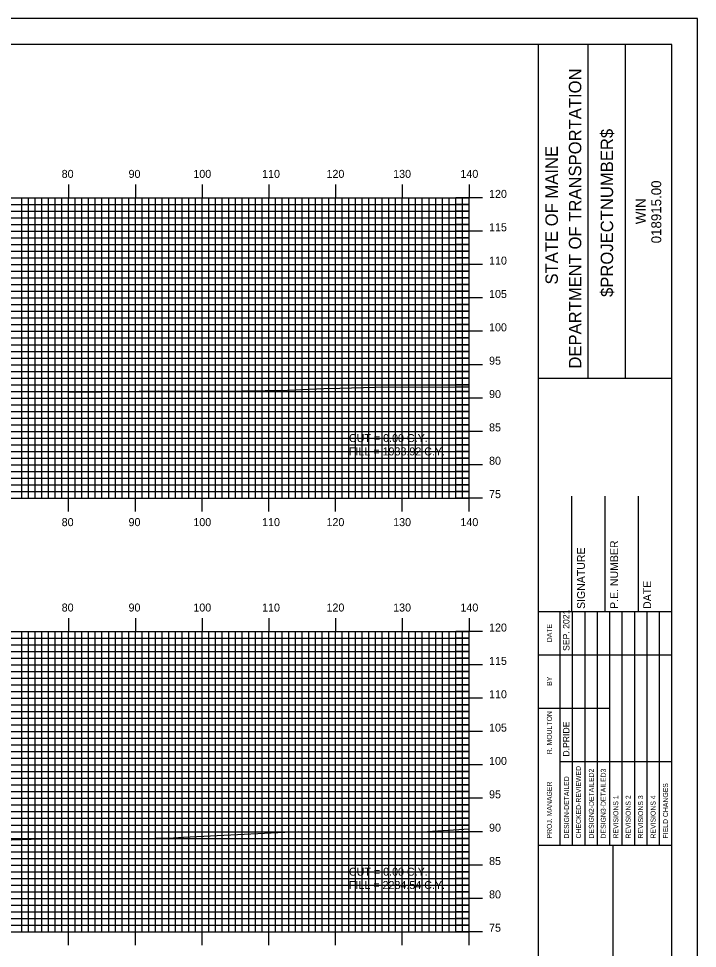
# Model space of a CAD drawing. Extents: x 485 to 829, y -1658 to -1438.
# Drawn here: x 723.6 to 825.3, y -1577.1 to -1437.7 of the extents above; entities that cross this region are included whole.
import ezdxf

# ---------------------------------------------------------------- set-up
doc = ezdxf.new("R2010")
doc.units = 0
for name, color, linetype in [('BORDER', 7, 'Continuous'), ('D_Text_Standard', 7, 'Continuous'), ('H_V ANNOTATION', 7, 'Continuous'), ('MAJOR', 7, 'Continuous'), ('MINOR', 7, 'Continuous'), ('PLOT BOUNDARY', 7, 'Continuous'), ('S_Roadway_Centerline', 7, 'Continuous')]:
    doc.layers.add(name, color=color, linetype=linetype)

msp = doc.modelspace()

# ---------------------------------------------------------------- linework, layer by layer
at = {"layer": 'BORDER'}
for p, q in [((801.53, -1651.6), (801.53, -1441.6)), ((808.99, -1491.61), (808.99, -1441.61)), ((814.58, -1491.61), (814.58, -1441.61)), ((801.54, -1491.62), (821.53, -1491.62)), ((806.53, -1526.6), (806.53, -1509.3)), ((811.53, -1526.6), (811.53, -1509.3)), ((816.53, -1526.6), (816.53, -1509.3)), ((801.53, -1526.6), (821.53, -1526.6)), ((801.53, -1561.6), (821.53, -1561.6)), ((812.72, -1631.6), (812.72, -1561.6))]:
    msp.add_line(p, q, dxfattribs=at)
msp.add_lwpolyline([(501.53, -1651.6), (821.53, -1651.6), (821.53, -1441.6), (501.53, -1441.6)], close=True, dxfattribs=at)
for points in [[(804.76, -1533.1), (804.76, -1526.6)], [(806.63, -1561.59), (806.63, -1526.6)], [(808.49, -1526.6), (808.49, -1561.59)], [(810.36, -1561.59), (810.36, -1526.6)], [(812.22, -1561.59), (812.22, -1526.6)], [(814.08, -1561.59), (814.08, -1526.6)], [(815.95, -1561.59), (815.95, -1526.6)], [(817.81, -1561.59), (817.81, -1526.6)], [(819.67, -1561.59), (819.67, -1526.6)], [(804.77, -1561.59), (804.77, -1528.01)], [(801.53, -1533.1), (821.53, -1533.1)], [(801.53, -1541.1), (804.77, -1541.1)], [(804.76, -1541.1), (812.22, -1541.1)], [(804.76, -1549.1), (821.53, -1549.1)]]:
    msp.add_lwpolyline(points, dxfattribs=at)
at = {"layer": 'MAJOR'}
for p, q in [((731.13, -1462.6), (731.13, -1464.6)), ((741.13, -1462.6), (741.13, -1464.6)), ((751.13, -1462.6), (751.13, -1464.6)), ((761.13, -1462.6), (761.13, -1464.6)), ((771.13, -1462.6), (771.13, -1464.6)), ((781.13, -1462.6), (781.13, -1464.6)), ((791.13, -1462.6), (791.13, -1464.6)), ((511.13, -1464.6), (791.13, -1464.6)), ((511.13, -1464.6), (791.13, -1464.6)), ((731.13, -1509.6), (731.13, -1464.6)), ((741.13, -1509.6), (741.13, -1464.6)), ((751.13, -1509.6), (751.13, -1464.6)), ((761.13, -1509.6), (761.13, -1464.6)), ((771.13, -1509.6), (771.13, -1464.6)), ((781.13, -1509.6), (781.13, -1464.6)), ((793.14, -1464.6), (789.13, -1464.6)), ((791.13, -1509.6), (791.13, -1464.6)), ((791.13, -1509.6), (791.13, -1464.6)), ((511.13, -1469.6), (791.13, -1469.6)), ((793.14, -1469.6), (789.13, -1469.6)), ((511.13, -1474.6), (791.13, -1474.6)), ((793.14, -1474.6), (789.13, -1474.6)), ((511.13, -1479.6), (791.13, -1479.6)), ((793.14, -1479.6), (789.13, -1479.6)), ((511.13, -1484.6), (791.13, -1484.6)), ((793.14, -1484.6), (789.13, -1484.6)), ((511.13, -1489.6), (791.13, -1489.6)), ((793.14, -1489.6), (789.13, -1489.6)), ((511.13, -1494.6), (791.13, -1494.6)), ((793.14, -1494.6), (789.13, -1494.6)), ((511.13, -1499.6), (791.13, -1499.6)), ((793.14, -1499.6), (789.13, -1499.6)), ((511.13, -1504.6), (791.13, -1504.6)), ((793.14, -1504.6), (789.13, -1504.6)), ((511.13, -1509.6), (791.13, -1509.6)), ((511.13, -1509.6), (791.13, -1509.6)), ((731.13, -1511.61), (731.13, -1509.6)), ((741.13, -1511.61), (741.13, -1509.6)), ((751.13, -1511.61), (751.13, -1509.6)), ((761.13, -1511.61), (761.13, -1509.6)), ((771.13, -1511.61), (771.13, -1509.6)), ((781.13, -1511.61), (781.13, -1509.6)), ((793.14, -1509.6), (789.13, -1509.6)), ((791.13, -1511.61), (791.13, -1509.6)), ((731.13, -1527.6), (731.13, -1529.6)), ((741.13, -1527.6), (741.13, -1529.6)), ((751.13, -1527.6), (751.13, -1529.6)), ((761.13, -1527.6), (761.13, -1529.6)), ((771.13, -1527.6), (771.13, -1529.6)), ((781.13, -1527.6), (781.13, -1529.6)), ((791.13, -1527.6), (791.13, -1529.6)), ((511.13, -1529.6), (791.13, -1529.6)), ((511.13, -1529.6), (791.13, -1529.6)), ((731.13, -1574.6), (731.13, -1529.6)), ((741.13, -1574.6), (741.13, -1529.6)), ((751.13, -1574.6), (751.13, -1529.6)), ((761.13, -1574.6), (761.13, -1529.6)), ((771.13, -1574.6), (771.13, -1529.6)), ((781.13, -1574.6), (781.13, -1529.6)), ((793.14, -1529.6), (789.13, -1529.6)), ((791.13, -1574.6), (791.13, -1529.6)), ((791.13, -1574.6), (791.13, -1529.6)), ((511.13, -1534.6), (791.13, -1534.6)), ((793.14, -1534.6), (789.13, -1534.6)), ((511.13, -1539.6), (791.13, -1539.6)), ((793.14, -1539.6), (789.13, -1539.6)), ((511.13, -1544.6), (791.13, -1544.6)), ((793.14, -1544.6), (789.13, -1544.6)), ((511.13, -1549.6), (791.13, -1549.6)), ((793.14, -1549.6), (789.13, -1549.6)), ((511.13, -1554.6), (791.13, -1554.6)), ((793.14, -1554.6), (789.13, -1554.6)), ((511.13, -1559.6), (791.13, -1559.6)), ((793.14, -1559.6), (789.13, -1559.6)), ((511.13, -1564.6), (791.13, -1564.6)), ((793.14, -1564.6), (789.13, -1564.6)), ((511.13, -1569.6), (791.13, -1569.6)), ((793.14, -1569.6), (789.13, -1569.6)), ((511.13, -1574.6), (791.13, -1574.6)), ((511.13, -1574.6), (791.13, -1574.6)), ((731.13, -1576.61), (731.13, -1574.6)), ((741.13, -1576.61), (741.13, -1574.6)), ((751.13, -1576.61), (751.13, -1574.6)), ((761.13, -1576.61), (761.13, -1574.6)), ((771.13, -1576.61), (771.13, -1574.6)), ((781.13, -1576.61), (781.13, -1574.6)), ((793.14, -1574.6), (789.13, -1574.6)), ((791.13, -1576.61), (791.13, -1574.6))]:
    msp.add_line(p, q, dxfattribs=at)
at = {"layer": 'MINOR'}
for p, q in [((724.13, -1509.6), (724.13, -1464.6)), ((725.13, -1509.6), (725.13, -1464.6)), ((726.13, -1509.6), (726.13, -1464.6)), ((727.13, -1509.6), (727.13, -1464.6)), ((728.13, -1509.6), (728.13, -1464.6)), ((729.13, -1509.6), (729.13, -1464.6)), ((730.13, -1509.6), (730.13, -1464.6)), ((732.13, -1509.6), (732.13, -1464.6)), ((733.13, -1509.6), (733.13, -1464.6)), ((734.13, -1509.6), (734.13, -1464.6)), ((735.13, -1509.6), (735.13, -1464.6)), ((736.13, -1509.6), (736.13, -1464.6)), ((737.13, -1509.6), (737.13, -1464.6)), ((738.13, -1509.6), (738.13, -1464.6)), ((739.13, -1509.6), (739.13, -1464.6)), ((740.13, -1509.6), (740.13, -1464.6)), ((742.13, -1509.6), (742.13, -1464.6)), ((743.13, -1509.6), (743.13, -1464.6)), ((744.13, -1509.6), (744.13, -1464.6)), ((745.13, -1509.6), (745.13, -1464.6)), ((746.13, -1509.6), (746.13, -1464.6)), ((747.13, -1509.6), (747.13, -1464.6)), ((748.13, -1509.6), (748.13, -1464.6)), ((749.13, -1509.6), (749.13, -1464.6)), ((750.13, -1509.6), (750.13, -1464.6)), ((752.13, -1509.6), (752.13, -1464.6)), ((753.13, -1509.6), (753.13, -1464.6)), ((754.13, -1509.6), (754.13, -1464.6)), ((755.13, -1509.6), (755.13, -1464.6)), ((756.13, -1509.6), (756.13, -1464.6)), ((757.13, -1509.6), (757.13, -1464.6)), ((758.13, -1509.6), (758.13, -1464.6)), ((759.13, -1509.6), (759.13, -1464.6)), ((760.13, -1509.6), (760.13, -1464.6)), ((762.13, -1509.6), (762.13, -1464.6)), ((763.13, -1509.6), (763.13, -1464.6)), ((764.13, -1509.6), (764.13, -1464.6)), ((765.13, -1509.6), (765.13, -1464.6)), ((766.13, -1509.6), (766.13, -1464.6)), ((767.13, -1509.6), (767.13, -1464.6)), ((768.13, -1509.6), (768.13, -1464.6)), ((769.13, -1509.6), (769.13, -1464.6)), ((770.13, -1509.6), (770.13, -1464.6)), ((772.13, -1509.6), (772.13, -1464.6)), ((773.13, -1509.6), (773.13, -1464.6)), ((774.13, -1509.6), (774.13, -1464.6)), ((775.13, -1509.6), (775.13, -1464.6)), ((776.13, -1509.6), (776.13, -1464.6)), ((777.13, -1509.6), (777.13, -1464.6)), ((778.13, -1509.6), (778.13, -1464.6)), ((779.13, -1509.6), (779.13, -1464.6)), ((780.13, -1509.6), (780.13, -1464.6)), ((782.13, -1509.6), (782.13, -1464.6)), ((783.13, -1509.6), (783.13, -1464.6)), ((784.13, -1509.6), (784.13, -1464.6)), ((785.13, -1509.6), (785.13, -1464.6)), ((786.13, -1509.6), (786.13, -1464.6)), ((787.13, -1509.6), (787.13, -1464.6)), ((788.13, -1509.6), (788.13, -1464.6)), ((789.13, -1509.6), (789.13, -1464.6)), ((790.13, -1509.6), (790.13, -1464.6)), ((511.13, -1465.6), (791.13, -1465.6)), ((791.13, -1465.6), (789.13, -1465.6)), ((511.13, -1466.6), (791.13, -1466.6)), ((511.13, -1467.6), (791.13, -1467.6)), ((791.13, -1466.6), (789.13, -1466.6)), ((791.13, -1467.6), (789.13, -1467.6)), ((511.13, -1468.6), (791.13, -1468.6)), ((791.13, -1468.6), (789.13, -1468.6)), ((511.13, -1470.6), (791.13, -1470.6)), ((511.13, -1471.6), (791.13, -1471.6)), ((791.13, -1470.6), (789.13, -1470.6)), ((791.13, -1471.6), (789.13, -1471.6)), ((511.13, -1472.6), (791.13, -1472.6)), ((791.13, -1472.6), (789.13, -1472.6)), ((511.13, -1473.6), (791.13, -1473.6)), ((791.13, -1473.6), (789.13, -1473.6)), ((511.13, -1475.6), (791.13, -1475.6)), ((791.13, -1475.6), (789.13, -1475.6)), ((511.13, -1476.6), (791.13, -1476.6)), ((791.13, -1476.6), (789.13, -1476.6)), ((511.13, -1477.6), (791.13, -1477.6)), ((511.13, -1478.6), (791.13, -1478.6)), ((791.13, -1477.6), (789.13, -1477.6)), ((791.13, -1478.6), (789.13, -1478.6)), ((511.13, -1480.6), (791.13, -1480.6)), ((791.13, -1480.6), (789.13, -1480.6)), ((511.13, -1481.6), (791.13, -1481.6)), ((511.13, -1482.6), (791.13, -1482.6)), ((791.13, -1481.6), (789.13, -1481.6)), ((791.13, -1482.6), (789.13, -1482.6)), ((511.13, -1483.6), (791.13, -1483.6)), ((791.13, -1483.6), (789.13, -1483.6)), ((511.13, -1485.6), (791.13, -1485.6)), ((791.13, -1485.6), (789.13, -1485.6)), ((511.13, -1486.6), (791.13, -1486.6)), ((791.13, -1486.6), (789.13, -1486.6)), ((511.13, -1487.6), (791.13, -1487.6)), ((791.13, -1487.6), (789.13, -1487.6)), ((511.13, -1488.6), (791.13, -1488.6)), ((791.13, -1488.6), (789.13, -1488.6)), ((511.13, -1490.6), (791.13, -1490.6)), ((791.13, -1490.6), (789.13, -1490.6)), ((511.13, -1491.6), (791.13, -1491.6)), ((511.13, -1492.6), (791.13, -1492.6)), ((791.13, -1491.6), (789.13, -1491.6)), ((791.13, -1492.6), (789.13, -1492.6)), ((511.13, -1493.6), (791.13, -1493.6)), ((791.13, -1493.6), (789.13, -1493.6)), ((511.13, -1495.6), (791.13, -1495.6)), ((511.13, -1496.6), (791.13, -1496.6)), ((791.13, -1495.6), (789.13, -1495.6)), ((791.13, -1496.6), (789.13, -1496.6)), ((511.13, -1497.6), (791.13, -1497.6)), ((791.13, -1497.6), (789.13, -1497.6)), ((511.13, -1498.6), (791.13, -1498.6)), ((791.13, -1498.6), (789.13, -1498.6)), ((511.13, -1500.6), (791.13, -1500.6)), ((791.13, -1500.6), (789.13, -1500.6)), ((511.13, -1501.6), (791.13, -1501.6)), ((791.13, -1501.6), (789.13, -1501.6)), ((511.13, -1502.6), (791.13, -1502.6)), ((511.13, -1503.6), (791.13, -1503.6)), ((791.13, -1502.6), (789.13, -1502.6)), ((791.13, -1503.6), (789.13, -1503.6)), ((511.13, -1505.6), (791.13, -1505.6)), ((511.13, -1506.6), (791.13, -1506.6)), ((791.13, -1505.6), (789.13, -1505.6)), ((791.13, -1506.6), (789.13, -1506.6)), ((511.13, -1507.6), (791.13, -1507.6)), ((791.13, -1507.6), (789.13, -1507.6)), ((511.13, -1508.6), (791.13, -1508.6)), ((791.13, -1508.6), (789.13, -1508.6)), ((724.13, -1574.6), (724.13, -1529.6)), ((725.13, -1574.6), (725.13, -1529.6)), ((726.13, -1574.6), (726.13, -1529.6)), ((727.13, -1574.6), (727.13, -1529.6)), ((728.13, -1574.6), (728.13, -1529.6)), ((729.13, -1574.6), (729.13, -1529.6)), ((730.13, -1574.6), (730.13, -1529.6)), ((732.13, -1574.6), (732.13, -1529.6)), ((733.13, -1574.6), (733.13, -1529.6)), ((734.13, -1574.6), (734.13, -1529.6)), ((735.13, -1574.6), (735.13, -1529.6)), ((736.13, -1574.6), (736.13, -1529.6)), ((737.13, -1574.6), (737.13, -1529.6)), ((738.13, -1574.6), (738.13, -1529.6)), ((739.13, -1574.6), (739.13, -1529.6)), ((740.13, -1574.6), (740.13, -1529.6)), ((742.13, -1574.6), (742.13, -1529.6)), ((743.13, -1574.6), (743.13, -1529.6)), ((744.13, -1574.6), (744.13, -1529.6)), ((745.13, -1574.6), (745.13, -1529.6)), ((746.13, -1574.6), (746.13, -1529.6)), ((747.13, -1574.6), (747.13, -1529.6)), ((748.13, -1574.6), (748.13, -1529.6)), ((749.13, -1574.6), (749.13, -1529.6)), ((750.13, -1574.6), (750.13, -1529.6)), ((752.13, -1574.6), (752.13, -1529.6)), ((753.13, -1574.6), (753.13, -1529.6)), ((754.13, -1574.6), (754.13, -1529.6)), ((755.13, -1574.6), (755.13, -1529.6)), ((756.13, -1574.6), (756.13, -1529.6)), ((757.13, -1574.6), (757.13, -1529.6)), ((758.13, -1574.6), (758.13, -1529.6)), ((759.13, -1574.6), (759.13, -1529.6)), ((760.13, -1574.6), (760.13, -1529.6)), ((762.13, -1574.6), (762.13, -1529.6)), ((763.13, -1574.6), (763.13, -1529.6)), ((764.13, -1574.6), (764.13, -1529.6)), ((765.13, -1574.6), (765.13, -1529.6)), ((766.13, -1574.6), (766.13, -1529.6)), ((767.13, -1574.6), (767.13, -1529.6)), ((768.13, -1574.6), (768.13, -1529.6)), ((769.13, -1574.6), (769.13, -1529.6)), ((770.13, -1574.6), (770.13, -1529.6)), ((772.13, -1574.6), (772.13, -1529.6)), ((773.13, -1574.6), (773.13, -1529.6)), ((774.13, -1574.6), (774.13, -1529.6)), ((775.13, -1574.6), (775.13, -1529.6)), ((776.13, -1574.6), (776.13, -1529.6)), ((777.13, -1574.6), (777.13, -1529.6)), ((778.13, -1574.6), (778.13, -1529.6)), ((779.13, -1574.6), (779.13, -1529.6)), ((780.13, -1574.6), (780.13, -1529.6)), ((782.13, -1574.6), (782.13, -1529.6)), ((783.13, -1574.6), (783.13, -1529.6)), ((784.13, -1574.6), (784.13, -1529.6)), ((785.13, -1574.6), (785.13, -1529.6)), ((786.13, -1574.6), (786.13, -1529.6)), ((787.13, -1574.6), (787.13, -1529.6)), ((788.13, -1574.6), (788.13, -1529.6)), ((789.13, -1574.6), (789.13, -1529.6)), ((790.13, -1574.6), (790.13, -1529.6)), ((511.13, -1530.6), (791.13, -1530.6)), ((511.13, -1531.6), (791.13, -1531.6)), ((791.13, -1530.6), (789.13, -1530.6)), ((791.13, -1531.6), (789.13, -1531.6)), ((511.13, -1532.6), (791.13, -1532.6)), ((791.13, -1532.6), (789.13, -1532.6)), ((511.13, -1533.6), (791.13, -1533.6)), ((791.13, -1533.6), (789.13, -1533.6)), ((511.13, -1535.6), (791.13, -1535.6)), ((791.13, -1535.6), (789.13, -1535.6)), ((511.13, -1536.6), (791.13, -1536.6)), ((791.13, -1536.6), (789.13, -1536.6)), ((511.13, -1537.6), (791.13, -1537.6)), ((511.13, -1538.6), (791.13, -1538.6)), ((791.13, -1537.6), (789.13, -1537.6)), ((791.13, -1538.6), (789.13, -1538.6)), ((511.13, -1540.6), (791.13, -1540.6)), ((791.13, -1540.6), (789.13, -1540.6)), ((511.13, -1541.6), (791.13, -1541.6)), ((511.13, -1542.6), (791.13, -1542.6)), ((791.13, -1541.6), (789.13, -1541.6)), ((791.13, -1542.6), (789.13, -1542.6)), ((511.13, -1543.6), (791.13, -1543.6)), ((791.13, -1543.6), (789.13, -1543.6)), ((511.13, -1545.6), (791.13, -1545.6)), ((791.13, -1545.6), (789.13, -1545.6)), ((511.13, -1546.6), (791.13, -1546.6)), ((791.13, -1546.6), (789.13, -1546.6)), ((511.13, -1547.6), (791.13, -1547.6)), ((791.13, -1547.6), (789.13, -1547.6)), ((511.13, -1548.6), (791.13, -1548.6)), ((791.13, -1548.6), (789.13, -1548.6)), ((511.13, -1550.6), (791.13, -1550.6)), ((791.13, -1550.6), (789.13, -1550.6)), ((511.13, -1551.6), (791.13, -1551.6)), ((511.13, -1552.6), (791.13, -1552.6)), ((791.13, -1551.6), (789.13, -1551.6)), ((791.13, -1552.6), (789.13, -1552.6)), ((511.13, -1553.6), (791.13, -1553.6)), ((791.13, -1553.6), (789.13, -1553.6)), ((511.13, -1555.6), (791.13, -1555.6)), ((511.13, -1556.6), (791.13, -1556.6)), ((791.13, -1555.6), (789.13, -1555.6)), ((791.13, -1556.6), (789.13, -1556.6)), ((511.13, -1557.6), (791.13, -1557.6)), ((791.13, -1557.6), (789.13, -1557.6)), ((511.13, -1558.6), (791.13, -1558.6)), ((791.13, -1558.6), (789.13, -1558.6)), ((511.13, -1560.6), (791.13, -1560.6)), ((791.13, -1560.6), (789.13, -1560.6)), ((511.13, -1561.6), (791.13, -1561.6)), ((791.13, -1561.6), (789.13, -1561.6)), ((511.13, -1562.6), (791.13, -1562.6)), ((511.13, -1563.6), (791.13, -1563.6)), ((791.13, -1562.6), (789.13, -1562.6)), ((791.13, -1563.6), (789.13, -1563.6)), ((511.13, -1565.6), (791.13, -1565.6)), ((791.13, -1565.6), (789.13, -1565.6)), ((511.13, -1566.6), (791.13, -1566.6)), ((511.13, -1567.6), (791.13, -1567.6)), ((791.13, -1566.6), (789.13, -1566.6)), ((791.13, -1567.6), (789.13, -1567.6)), ((511.13, -1568.6), (791.13, -1568.6)), ((791.13, -1568.6), (789.13, -1568.6)), ((511.13, -1570.6), (791.13, -1570.6)), ((791.13, -1570.6), (789.13, -1570.6)), ((511.13, -1571.6), (791.13, -1571.6)), ((791.13, -1571.6), (789.13, -1571.6)), ((511.13, -1572.6), (791.13, -1572.6)), ((791.13, -1572.6), (789.13, -1572.6)), ((511.13, -1573.6), (791.13, -1573.6)), ((791.13, -1573.6), (789.13, -1573.6))]:
    msp.add_line(p, q, dxfattribs=at)
at = {"layer": 'PLOT BOUNDARY'}
msp.add_lwpolyline([(485.35, -1657.72), (825.35, -1657.72), (825.35, -1437.72), (485.35, -1437.72)], close=True, dxfattribs=at)
at = {"layer": 'S_Roadway_Centerline'}
for points in [[(616.3, -1496.46), (624.98, -1495.99), (629.65, -1495.69), (631.37, -1495.68), (634.77, -1495.54), (648.43, -1495.02), (654.32, -1494.89), (666.18, -1494.54), (672.13, -1494.58), (682.88, -1494.63), (692.81, -1494.19), (701.22, -1494.02), (717.87, -1493.58), (719.17, -1493.55), (731.05, -1493.68), (736.02, -1493.66), (744.54, -1493.54), (753.83, -1493.55), (763.95, -1493.4), (769.39, -1493.17), (771.76, -1493.11), (777.05, -1492.99), (789.2, -1492.93), (791.13, -1492.91)], [(615.91, -1562.69), (624.29, -1562.57), (635.21, -1562.36), (640.02, -1562.14), (653.7, -1561.78), (660.67, -1561.89), (672.76, -1561.52), (674.18, -1561.52), (691.05, -1561.68), (707.38, -1561.38), (708.44, -1561.35), (709.09, -1561.34), (721.14, -1560.85), (728.42, -1560.62), (733.48, -1560.61), (744.15, -1560.57), (745.48, -1560.57), (746.09, -1560.57), (748.34, -1560.42), (765.53, -1559.55), (778.36, -1559.61), (784.09, -1559.62), (791.13, -1559.17)]]:
    msp.add_lwpolyline(points, dxfattribs=at)

# ---------------------------------------------------------------- texts
at = {"layer": 'BORDER'}
for s, height, p in [('DEPARTMENT OF TRANSPORTATION', 1.8635, (807.95, -1490.19)), ('$PROJECTNUMBER$', 1.8635, (812.72, -1479.45)), ('STATE OF MAINE', 1.8635, (804.44, -1477.58)), ('018915.00', 1.491, (819.93, -1471.41)), ('WIN', 1.491, (817.61, -1468.54)), ('P.E. NUMBER', 1.1811, (813.46, -1526.21)), ('SIGNATURE', 1.181, (808.5, -1526.21)), ('DATE', 1.181, (818.42, -1526.21)), ('SEP. 2021', 0.969, (806.18, -1532.51)), ('DATE', 0.743, (803.54, -1531.19)), ('BY', 0.743, (803.54, -1537.73)), ('R. MOULTON', 0.745, (803.54, -1547.99)), ('D.PRIDE', 0.969, (806.18, -1548.35)), ('CHECKED-REVIEWED', 0.7455, (807.9, -1560.62)), ('DESIGN2-DETAILED2', 0.7455, (809.83, -1560.62)), ('DESIGN3-DETAILED3', 0.7455, (811.62, -1560.62)), ('PROJ. MANAGER', 0.7455, (803.54, -1560.62)), ('DESIGN-DETAILED', 0.7455, (806.11, -1560.62)), ('FIELD CHANGES', 0.7455, (820.94, -1560.62)), ('REVISIONS 1', 0.7455, (813.49, -1560.62)), ('REVISIONS 2', 0.7455, (815.35, -1560.62)), ('REVISIONS 3', 0.7455, (817.21, -1560.62)), ('REVISIONS 4', 0.7455, (819.08, -1560.62))]:
    msp.add_text(s, height=height, rotation=90, dxfattribs=at).set_placement(p)
at = {"layer": 'D_Text_Standard'}
for s, p in [('CUT = 0.00 C.Y.', (773.13, -1501.2)), ('FILL = 1933.92 C.Y.', (773.13, -1503.2)), ('CUT = 0.00 C.Y.', (773.13, -1566.2)), ('FILL = 2284.54 C.Y.', (773.13, -1568.2))]:
    msp.add_text(s, height=1.2, dxfattribs=at).set_placement(p)
at = {"layer": 'H_V ANNOTATION'}
for s, p in [('80', (730.09, -1461.6)), ('90', (740.11, -1461.6)), ('100', (749.82, -1461.6)), ('110', (760.12, -1461.6)), ('120', (769.77, -1461.6)), ('130', (779.76, -1461.6)), ('140', (789.84, -1461.6)), ('120', (794.13, -1464.6)), ('115', (794.13, -1469.6)), ('110', (794.13, -1474.6)), ('105', (794.13, -1479.6)), ('100', (794.13, -1484.6)), ('95', (794.13, -1489.6)), ('90', (794.13, -1494.6)), ('85', (794.13, -1499.6)), ('80', (794.13, -1504.6)), ('75', (794.13, -1509.6)), ('80', (730.09, -1513.8)), ('90', (740.11, -1513.8)), ('100', (749.82, -1513.8)), ('110', (760.12, -1513.8)), ('120', (769.77, -1513.8)), ('130', (779.76, -1513.8)), ('140', (789.84, -1513.8)), ('80', (730.09, -1526.6)), ('90', (740.11, -1526.6)), ('100', (749.82, -1526.6)), ('110', (760.12, -1526.6)), ('120', (769.77, -1526.6)), ('130', (779.76, -1526.6)), ('140', (789.84, -1526.6)), ('120', (794.13, -1529.6)), ('115', (794.13, -1534.6)), ('110', (794.13, -1539.6)), ('105', (794.13, -1544.6)), ('100', (794.13, -1549.6)), ('95', (794.13, -1554.6)), ('90', (794.13, -1559.6)), ('85', (794.13, -1564.6)), ('80', (794.13, -1569.6)), ('75', (794.13, -1574.6))]:
    msp.add_text(s, height=1.2, dxfattribs=at).set_placement(p)

doc.saveas('drawing.dxf')
